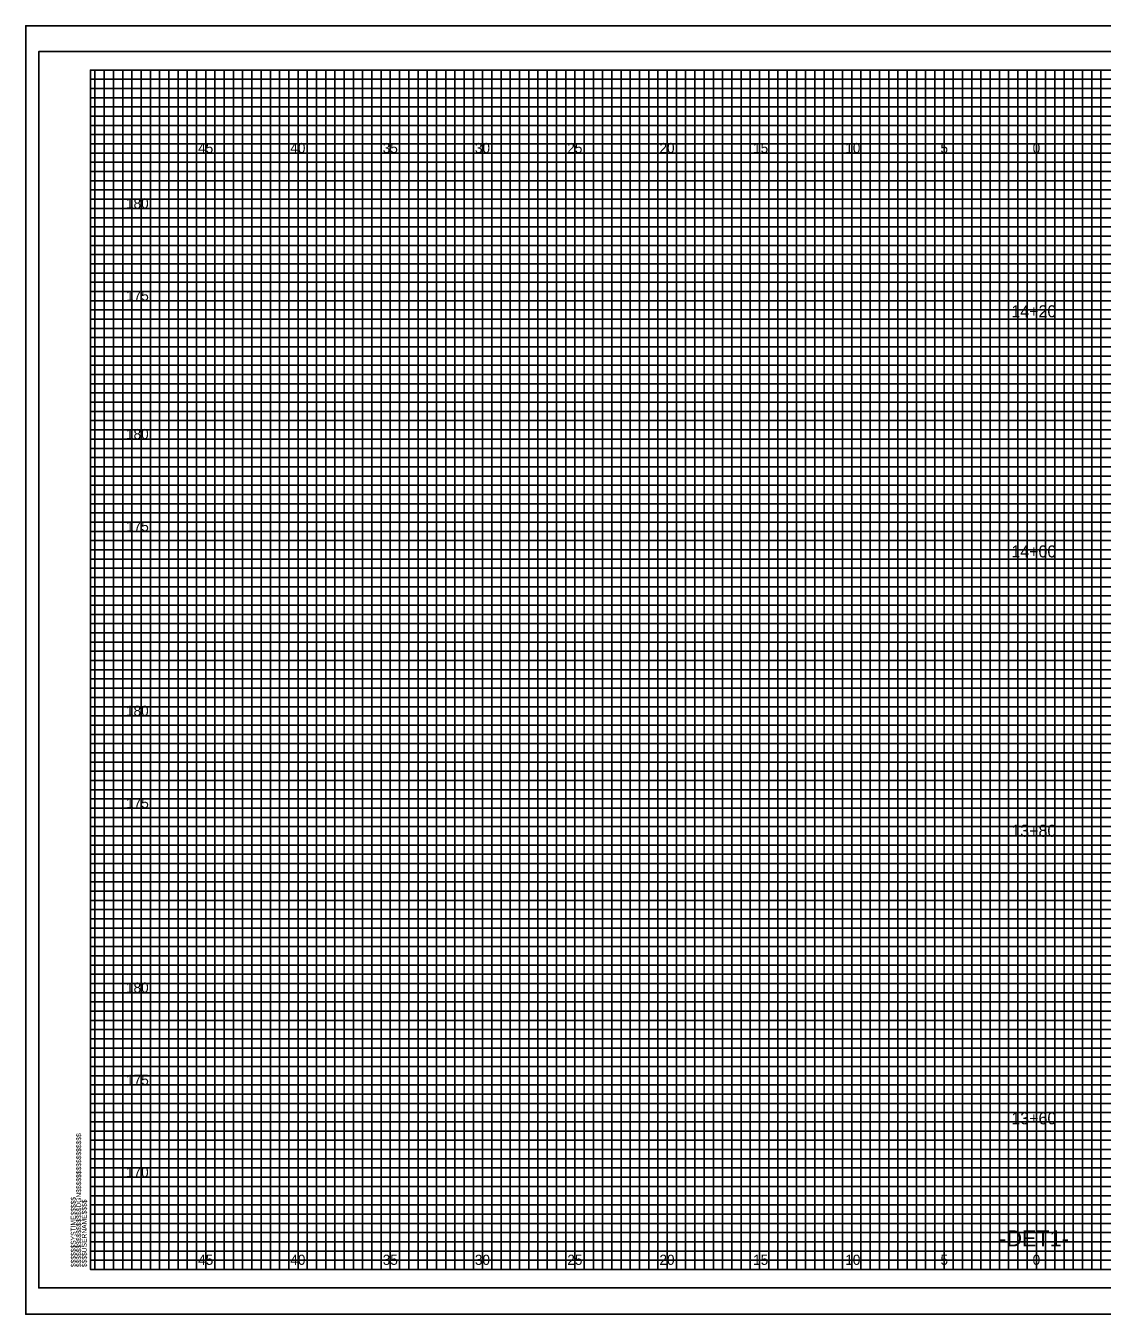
# Model space of a CAD drawing. Extents: x -4 to 103, y -2 to 280.
# Drawn here: x -3.5 to 54.8, y 68.4 to 138.2 of the extents above; entities that cross this region are included whole.
import ezdxf

# ---------------------------------------------------------------- set-up
doc = ezdxf.new("R2010")
doc.units = 0
for name, color, linetype in [('Exist XS Center Line Elevation Label', 7, 'Continuous'), ('Old_Level_63', 7, 'Continuous'), ('Prop XS Dump Level', 7, 'Continuous'), ('Prop XS EOT Tick Mark', 7, 'Continuous'), ('Prop XS Finish Grade Earthwork', 7, 'Continuous'), ('Prop XS Pvmt Edge Slope', 7, 'Continuous'), ('Prop XS SE Text', 7, 'Continuous'), ('Prop XS Subgrade Earthwork', 7, 'Continuous'), ('Sheet Cutting Line CELL', 7, 'Continuous'), ('Sheet Plot Border Inside CELL', 7, 'Continuous'), ('Sheet Plot Border Outside CELL', 7, 'Continuous')]:
    doc.layers.add(name, color=color, linetype=linetype)

msp = doc.modelspace()

# ---------------------------------------------------------------- linework, layer by layer
at = {"layer": 'Exist XS Center Line Elevation Label'}
for points in [[(1.25, 70.825), (1.25, 135.825), (3.75, 135.825), (3.75, 70.825), (6.25, 70.825), (6.25, 135.825), (8.75, 135.825), (8.75, 70.825), (11.25, 70.825), (11.25, 135.825), (13.75, 135.825), (13.75, 70.825), (16.25, 70.825), (16.25, 135.825), (18.75, 135.825), (18.75, 70.825), (21.25, 70.825), (21.25, 135.825), (23.75, 135.825), (23.75, 70.825), (26.25, 70.825), (26.25, 135.825), (28.75, 135.825), (28.75, 70.825), (31.25, 70.825), (31.25, 135.825), (33.75, 135.825), (33.75, 70.825), (36.25, 70.825), (36.25, 135.825), (38.75, 135.825), (38.75, 70.825), (41.25, 70.825), (41.25, 135.825), (43.75, 135.825), (43.75, 70.825), (46.25, 70.825), (46.25, 135.825), (48.75, 135.825), (48.75, 70.825), (51.25, 70.825), (51.25, 135.825), (53.75, 135.825), (53.75, 70.825)], [(102.5, 130.825), (0, 130.825), (0, 133.325), (74.25, 133.325)], [(102.5, 125.825), (0, 125.825), (0, 128.325), (102.5, 128.325)], [(102.5, 120.825), (0, 120.825), (0, 123.325), (102.5, 123.325)], [(102.5, 115.825), (0, 115.825), (0, 118.325), (102.5, 118.325)], [(102.5, 110.825), (0, 110.825), (0, 113.325), (102.5, 113.325)], [(102.5, 105.825), (0, 105.825), (0, 108.325), (102.5, 108.325)], [(102.5, 100.825), (0, 100.825), (0, 103.325), (102.5, 103.325)], [(102.5, 95.825), (0, 95.825), (0, 98.325), (102.5, 98.325)], [(102.5, 90.825), (0, 90.825), (0, 93.325), (102.5, 93.325)], [(102.5, 85.825), (0, 85.825), (0, 88.325), (102.5, 88.325)], [(102.5, 80.825), (0, 80.825), (0, 83.325), (102.5, 83.325)], [(102.5, 75.825), (0, 75.825), (0, 78.325), (102.5, 78.325)], [(0, 73.325), (102.5, 73.325)]]:
    msp.add_lwpolyline(points, dxfattribs=at)
at = {"layer": 'Old_Level_63'}
msp.add_lwpolyline([(102.5, 135.825), (0, 135.825), (0, 70.825), (102.5, 70.825)], close=True, dxfattribs=at)
at = {"layer": 'Prop XS Dump Level'}
for p, q in [((1.25, 70.825), (1.25, 135.825)), ((3.75, 70.825), (3.75, 135.825)), ((6.25, 70.825), (6.25, 135.825)), ((8.75, 70.825), (8.75, 135.825)), ((11.25, 70.825), (11.25, 135.825)), ((13.75, 70.825), (13.75, 135.825)), ((16.25, 70.825), (16.25, 135.825)), ((18.75, 70.825), (18.75, 135.825)), ((21.25, 70.825), (21.25, 135.825)), ((23.75, 70.825), (23.75, 135.825)), ((26.25, 70.825), (26.25, 135.825)), ((28.75, 70.825), (28.75, 135.825)), ((31.25, 70.825), (31.25, 135.825)), ((33.75, 70.825), (33.75, 135.825)), ((36.25, 70.825), (36.25, 135.825)), ((38.75, 70.825), (38.75, 135.825)), ((41.25, 70.825), (41.25, 135.825)), ((43.75, 70.825), (43.75, 135.825)), ((46.25, 70.825), (46.25, 135.825)), ((48.75, 70.825), (48.75, 135.825)), ((51.25, 70.825), (51.25, 135.825)), ((53.75, 70.825), (53.75, 135.825)), ((0, 133.325), (74.25, 133.325)), ((0, 130.825), (102.5, 130.825)), ((0, 128.325), (102.5, 128.325)), ((0, 125.825), (102.5, 125.825)), ((0, 123.325), (102.5, 123.325)), ((0, 120.825), (102.5, 120.825)), ((0, 118.325), (102.5, 118.325)), ((0, 115.825), (102.5, 115.825)), ((0, 113.325), (102.5, 113.325)), ((0, 110.825), (102.5, 110.825)), ((0, 108.325), (102.5, 108.325)), ((0, 105.825), (102.5, 105.825)), ((0, 103.325), (102.5, 103.325)), ((0, 100.825), (102.5, 100.825)), ((0, 98.325), (102.5, 98.325)), ((0, 95.825), (102.5, 95.825)), ((0, 93.325), (102.5, 93.325)), ((0, 90.825), (102.5, 90.825)), ((0, 88.325), (102.5, 88.325)), ((0, 85.825), (102.5, 85.825)), ((0, 83.325), (102.5, 83.325)), ((0, 80.825), (102.5, 80.825)), ((0, 78.325), (102.5, 78.325)), ((0, 75.825), (102.5, 75.825)), ((0, 73.325), (102.5, 73.325))]:
    msp.add_line(p, q, dxfattribs=at)
at = {"layer": 'Prop XS SE Text'}
for points in [[(0.25, 70.825), (0.25, 135.825), (0.75, 135.825), (0.75, 70.825), (1.75, 70.825), (1.75, 135.825), (2.25, 135.825), (2.25, 70.825), (2.75, 70.825), (2.75, 135.825), (3.25, 135.825), (3.25, 70.825), (4.25, 70.825), (4.25, 135.825), (4.75, 135.825), (4.75, 70.825), (5.25, 70.825), (5.25, 135.825), (5.75, 135.825), (5.75, 70.825), (6.75, 70.825), (6.75, 135.825), (7.25, 135.825), (7.25, 70.825), (7.75, 70.825), (7.75, 135.825), (8.25, 135.825), (8.25, 70.825), (9.25, 70.825), (9.25, 135.825), (9.75, 135.825), (9.75, 70.825), (10.25, 70.825), (10.25, 135.825), (10.75, 135.825), (10.75, 70.825), (11.75, 70.825), (11.75, 135.825), (12.25, 135.825), (12.25, 70.825), (12.75, 70.825), (12.75, 135.825), (13.25, 135.825), (13.25, 70.825), (14.25, 70.825), (14.25, 135.825), (14.75, 135.825), (14.75, 70.825), (15.75, 70.825), (15.25, 70.825), (15.25, 135.825), (15.75, 135.825), (15.75, 70.825), (16.75, 70.825), (16.75, 135.825), (17.25, 135.825), (17.25, 70.825), (17.75, 70.825), (17.75, 135.825), (18.25, 135.825), (18.25, 70.825), (19.25, 70.825), (19.25, 135.825), (19.75, 135.825), (19.75, 70.825), (20.25, 70.825), (20.25, 135.825), (20.75, 135.825), (20.75, 70.825), (21.75, 70.825), (21.75, 135.825), (22.25, 135.825), (22.25, 70.825), (22.75, 70.825), (22.75, 135.825), (23.25, 135.825), (23.25, 70.825), (24.25, 70.825), (24.25, 135.825), (24.75, 135.825), (24.75, 70.825), (25.25, 70.825), (25.25, 135.825), (25.75, 135.825), (25.75, 70.825), (26.75, 70.825), (26.75, 135.825), (27.25, 135.825), (27.25, 70.825), (27.75, 70.825), (27.75, 135.825), (28.25, 135.825), (28.25, 70.825), (29.25, 70.825), (29.25, 135.825), (29.75, 135.825), (29.75, 70.825), (30.25, 70.825), (30.25, 135.825), (30.75, 135.825), (30.75, 70.825)], [(30.75, 70.825), (31.75, 70.825), (31.75, 135.825), (32.25, 135.825), (32.25, 70.825), (32.75, 70.825), (32.75, 135.825), (33.25, 135.825), (33.25, 70.825), (34.25, 70.825), (34.25, 135.825), (34.75, 135.825), (34.75, 70.825), (35.25, 70.825), (35.25, 135.825), (35.75, 135.825), (35.75, 70.825), (36.75, 70.825), (36.75, 135.825), (37.25, 135.825), (37.25, 70.825), (37.75, 70.825), (37.75, 135.825), (37.75, 70.825)], [(38.25, 135.825), (38.25, 70.825), (39.25, 70.825), (39.25, 135.825), (39.75, 135.825), (39.75, 70.825), (40.25, 70.825), (40.25, 135.825), (40.75, 135.825), (40.75, 70.825), (41.75, 70.825), (41.75, 135.825), (42.25, 135.825), (42.25, 70.825), (42.75, 70.825), (42.75, 135.825), (43.25, 135.825), (43.25, 70.825), (43.75, 70.825), (44.25, 70.825), (44.25, 135.825), (44.75, 135.825), (44.75, 70.825), (45.25, 70.825), (45.25, 135.825), (45.75, 135.825), (45.75, 70.825), (46.75, 70.825), (46.75, 135.825), (47.25, 135.825), (47.25, 70.825), (47.75, 70.825), (47.75, 135.825), (48.25, 135.825), (48.25, 70.825), (49.25, 70.825), (49.25, 135.825), (49.75, 135.825), (49.75, 70.825), (50.25, 70.825), (50.25, 135.825), (50.75, 135.825), (50.75, 70.825), (51.75, 70.825), (51.75, 135.825), (52.25, 135.825), (52.25, 70.825), (52.75, 70.825), (52.75, 135.825), (53.25, 135.825), (53.25, 70.825), (54.25, 70.825), (54.25, 135.825), (54.75, 135.825), (54.75, 70.825), (55.25, 70.825)], [(0, 132.825), (0, 133.825), (74.25, 133.825), (74.25, 134.325), (0, 134.325), (0, 134.825), (74.25, 134.825), (74.25, 135.325), (0, 135.325)], [(102.5, 132.825), (0, 132.825)], [(102.5, 131.825), (0, 131.825), (0, 132.325), (102.5, 132.325)], [(102.5, 130.325), (0, 130.325), (0, 131.325), (102.5, 131.325)], [(102.5, 129.325), (0, 129.325), (0, 129.825), (102.5, 129.825)], [(102.5, 127.825), (0, 127.825), (0, 128.825), (102.5, 128.825)], [(102.5, 126.825), (0, 126.825), (0, 127.325), (102.5, 127.325)], [(102.5, 125.325), (0, 125.325), (0, 126.325), (102.5, 126.325)], [(102.5, 124.325), (0, 124.325), (0, 124.825), (102.5, 124.825)], [(0, 123.825), (102.5, 123.825)], [(102.5, 122.825), (0, 122.825)], [(102.5, 121.825), (0, 121.825), (0, 122.325), (102.5, 122.325)], [(102.5, 120.325), (0, 120.325), (0, 121.325), (102.5, 121.325)], [(102.5, 119.325), (0, 119.325), (0, 119.825), (102.5, 119.825)], [(102.5, 117.825), (0, 117.825), (0, 118.825), (102.5, 118.825)], [(102.5, 116.825), (0, 116.825), (0, 117.325), (102.5, 117.325)], [(102.5, 115.325), (0, 115.325), (0, 116.325), (102.5, 116.325)], [(102.5, 114.325), (0, 114.325), (0, 114.825), (102.5, 114.825)], [(102.5, 112.825), (0, 112.825), (0, 113.825), (102.5, 113.825)], [(102.5, 111.825), (0, 111.825), (0, 112.325), (102.5, 112.325)], [(102.5, 110.325), (0, 110.325), (0, 111.325), (102.5, 111.325)], [(102.5, 109.325), (0, 109.325), (0, 109.825), (102.5, 109.825)], [(102.5, 107.825), (0, 107.825), (0, 108.825), (102.5, 108.825)], [(102.5, 106.825), (0, 106.825), (0, 107.325), (102.5, 107.325)], [(102.5, 105.325), (0, 105.325), (0, 106.325), (102.5, 106.325)], [(102.5, 104.325), (0, 104.325), (0, 104.825), (102.5, 104.825)], [(102.5, 102.825), (0, 102.825), (0, 103.825), (102.5, 103.825)], [(102.5, 101.825), (0, 101.825), (0, 102.325)], [(0, 102.325), (102.5, 102.325)], [(102.5, 100.325), (0, 100.325), (0, 101.325), (102.5, 101.325)], [(102.5, 99.325), (0, 99.325), (0, 99.825), (102.5, 99.825)], [(102.5, 97.825), (0, 97.825), (0, 98.825), (102.5, 98.825)], [(102.5, 96.825), (0, 96.825), (0, 97.325), (102.5, 97.325)], [(102.5, 95.325), (0, 95.325), (0, 96.325), (102.5, 96.325)], [(102.5, 94.325), (0, 94.325), (0, 94.825), (102.5, 94.825)], [(102.5, 92.825), (0, 92.825), (0, 93.825), (102.5, 93.825)], [(102.5, 91.825), (0, 91.825), (0, 92.325), (102.5, 92.325)], [(102.5, 90.325), (0, 90.325), (0, 91.325), (102.5, 91.325)], [(102.5, 89.325), (0, 89.325), (0, 89.825), (102.5, 89.825)], [(102.5, 87.825), (0, 87.825), (0, 88.825), (102.5, 88.825)], [(102.5, 86.825), (0, 86.825), (0, 87.325), (102.5, 87.325)], [(102.5, 85.325), (0, 85.325), (0, 86.325), (102.5, 86.325)], [(102.5, 84.325), (0, 84.325), (0, 84.825), (102.5, 84.825)], [(102.5, 82.825), (0, 82.825), (0, 83.825), (102.5, 83.825)], [(102.5, 81.825), (0, 81.825), (0, 82.325), (102.5, 82.325)], [(102.5, 80.325), (0, 80.325), (0, 81.325), (102.5, 81.325)], [(102.5, 79.325), (0, 79.325), (0, 79.825), (102.5, 79.825)], [(102.5, 77.825), (0, 77.825), (0, 78.825), (102.5, 78.825)], [(102.5, 76.825), (0, 76.825), (0, 77.325), (102.5, 77.325)], [(102.5, 75.325), (0, 75.325), (0, 76.325), (102.5, 76.325)], [(102.5, 74.325), (0, 74.325), (0, 74.825), (102.5, 74.825)], [(102.5, 72.825), (0, 72.825), (0, 73.825), (102.5, 73.825)], [(102.5, 71.825), (0, 71.825), (0, 72.325), (102.5, 72.325)], [(0, 71.325), (102.5, 71.325)]]:
    msp.add_lwpolyline(points, dxfattribs=at)
at = {"layer": 'Sheet Cutting Line CELL'}
for p, q in [((-3.5, 138.225), (103.4, 138.225)), ((-3.5, 138.225), (-3.5, 68.4)), ((-3.5, 68.4), (103.4, 68.4))]:
    msp.add_line(p, q, dxfattribs=at)
at = {"layer": 'Sheet Plot Border Inside CELL'}
msp.add_lwpolyline([(103, 136.825), (-2.8, 136.825), (-2.8, 69.825), (103, 69.825)], close=True, dxfattribs=at)
at = {"layer": 'Sheet Plot Border Outside CELL'}
msp.add_lwpolyline([(103.4, 138.225), (-3.5, 138.225), (-3.5, 68.4), (103.4, 68.4)], close=True, dxfattribs=at)

# ---------------------------------------------------------------- texts
at = {"layer": 'Exist XS Center Line Elevation Label'}
msp.add_text('040397', height=0.0025, rotation=90, dxfattribs=at).set_placement((-0.001, 135.811))
at = {"layer": 'Old_Level_63'}
for s, p in [('$$$$$$$$$$$$$$$$DGN$$$$$$$$$$$$$$$$', (-0.5, 70.95)), ('$$$$$$SYSTIME$$$$$', (-0.797, 70.95)), ('$$$$USERNAME$$$$', (-0.2, 70.95))]:
    msp.add_text(s, height=0.2625, rotation=90, dxfattribs=at).set_placement(p)
at = {"layer": 'Prop XS EOT Tick Mark'}
for s, p in [('14+20', (49.893, 122.427)), ('14+00', (49.893, 109.414)), ('13+80', (49.893, 94.276)), ('13+60', (49.893, 78.691))]:
    msp.add_text(s, height=0.65, dxfattribs=at).set_placement(p)
at = {"layer": 'Prop XS Finish Grade Earthwork'}
msp.add_text('-DET1-', height=0.875, dxfattribs=at).set_placement((49.238, 72.075))
at = {"layer": 'Prop XS Pvmt Edge Slope'}
for s, p in [('45', (5.84, 131.325)), ('40', (10.831, 131.325)), ('35', (15.84, 131.325)), ('30', (20.831, 131.325)), ('25', (25.84, 131.325)), ('20', (30.831, 131.325)), ('15', (35.906, 131.325)), ('10', (40.897, 131.325)), ('5', (46.057, 131.325)), ('0', (51.049, 131.325)), ('0', (51.049, 131.325)), ('45', (5.84, 71.075)), ('40', (10.831, 71.075)), ('35', (15.84, 71.075)), ('30', (20.831, 71.075)), ('25', (25.84, 71.075)), ('20', (30.831, 71.075)), ('15', (35.906, 71.075)), ('10', (40.897, 71.075)), ('5', (46.057, 71.075)), ('0', (51.049, 71.075)), ('0', (51.049, 71.075))]:
    msp.add_text(s, height=0.55, dxfattribs=at).set_placement(p)
at = {"layer": 'Prop XS Subgrade Earthwork'}
for s, p in [('180', (1.93, 128.325)), ('175', (1.938, 123.325)), ('180', (1.93, 115.825)), ('175', (1.938, 110.825)), ('180', (1.93, 100.825)), ('175', (1.938, 95.825)), ('180', (1.93, 85.825)), ('175', (1.938, 80.825)), ('170', (1.93, 75.825))]:
    msp.add_text(s, height=0.55, dxfattribs=at).set_placement(p)

doc.saveas('drawing.dxf')
